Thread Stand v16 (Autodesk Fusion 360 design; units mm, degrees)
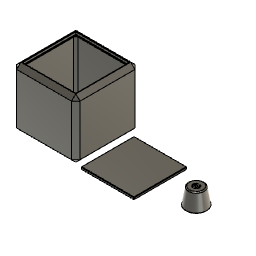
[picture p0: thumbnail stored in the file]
parameter "base_side_length" = 75
parameter "base_height" = 70
parameter "wire_hole_diameter" = 2.75 (= "wire_diameter + wire_hole_tolerance")
parameter "wire_hole_offset_from_corner" = 12
parameter "wire_hole_depth" = 30
parameter "spool_pin_diameter" = 6
parameter "spool_pin_height" = 20
parameter "big_chamfer_size" = 5
parameter "bottom_hole_offset" = 6
parameter "shell_thickness" = 4
parameter "bottom_hatch_side_length" = 63 (= "base_side_length - bottom_hole_offset * 2")
parameter "hatch_step_width" = 2
parameter "hatch_step_depth" = 3
parameter "hatch_side_tolerance" = 0.3
parameter "hatch_thickness_tolerance" = 0.2
parameter "wire_hole_tolerance" = 0.2
parameter "wire_diameter" = 2.55
parameter "spring_thickness" = 1.5
parameter "spring_gap" = 1
parameter "spring_bridge_width" = 2
parameter "cap_base" = 25
parameter "cap_base_taper" = 10
parameter "cap_height" = 20
sketch "Sketch2" plane through (0, 0, 0) normal (0, 0, 1) x axis (1, 0, 0)
  line L1 (-37.5, -37.5) -> (37.5, -37.5)
  line L2 (-37.5, 37.5) -> (-37.5, -37.5)
  line L3 (37.5, 37.5) -> (-37.5, 37.5)
  line L4 (37.5, -37.5) -> (37.5, 37.5)
  line L5 (-37.5, 37.5) -> (37.5, -37.5)
  line L6 (37.5, 37.5) -> (-37.5, -37.5)
  point P6 (0, 0)
  point P1 (0, 0)
  point P4 (-37.5, 37.5)
  point P5 (37.5, 37.5)
  point P3 (-37.5, -37.5)
  horizontal L1
  perpendicular L1 L2
  parallel L1 L3
  parallel L2 L4
  coincident L5 P6
  coincident L6 P6
  coincident P1 P6
  dimension "d7" distance P4 P5 = 75 (= "base_side_length")
  dimension "d8" distance P3 P4 = 75 (= "base_side_length")
extrude "Extrude2" new body sketch "Sketch2" profile of L1 L2 L3 L4 along normal blind 70 (= "base_height") bodies "Thread_Stand_Body"
sketch "Sketch3" plane through (0, 0, 70) normal (0, 0, 1) x axis (-1, 0, 0)
  line L1 (37.5, -37.5) -> (-37.5, -37.5)
  line L2 (37.5, 37.5) -> (37.5, -37.5)
  line L3 (-37.5, 37.5) -> (37.5, 37.5)
  line L4 (-37.5, -37.5) -> (-37.5, 37.5)
  line L5 (-37.5, 37.5) -> (37.5, -37.5)
  line L6 (37.5, 37.5) -> (-37.5, -37.5)
  circle C1 centre (29.0147, -29.0147) radius 1.375
  circle C2 centre (0, 0) radius 1.375
  point P3 (37.5, -37.5)
  point P7 (37.5, -37.5)
  point P5 (-37.5, 37.5)
  point P8 (-37.5, 37.5)
  point P6 (29.0147, -29.0147)
  point P2 (-37.5, -37.5)
  point P9 (-37.5, -37.5)
  point P4 (37.5, 37.5)
  point P10 (37.5, 37.5)
  point P1 (0, 0)
  point P11 (0, 0)
  coincident P3 P7
  coincident P5 P8
  coincident P6 L5
  coincident P2 P9
  coincident P4 P10
  coincident P1 P11
  dimension "d12" diameter C1 = 2.75 (= "wire_hole_diameter")
  dimension "d14" distance P6 P7 = 12 (= "wire_hole_offset_from_corner")
  dimension "d18" diameter C2 = 2.75 (= "wire_hole_diameter")
extrude "Extrude3" cut sketch "Sketch3" profile of C1 C2 no distance stored
chamfer "Chamfer1" distance 5 (= "big_chamfer_size")
chamfer "Chamfer2" distance 0.5
shell "Shell1" innerThickness 4 (= "shell_thickness")
sketch "Sketch4" plane through (0, 0, 0) normal (0, 0, -1) x axis (1, 0, 0)
  line L1 (-26.8431, -26.8431) -> (26.8431, -26.8431)
  line L2 (-26.8431, 26.8431) -> (-26.8431, -26.8431)
  line L3 (26.8431, 26.8431) -> (-26.8431, 26.8431)
  line L4 (26.8431, -26.8431) -> (26.8431, 26.8431)
  line L5 (32.5, -32.5) -> (-32.5, -32.5)
  line L6 (32.5, 32.5) -> (32.5, -32.5)
  line L7 (-32.5, 32.5) -> (32.5, 32.5)
  line L8 (-32.5, -32.5) -> (-32.5, 32.5)
  line L9 (31.5, -31.5) -> (-31.5, -31.5)
  line L10 (31.5, 31.5) -> (31.5, -31.5)
  line L11 (-31.5, 31.5) -> (31.5, 31.5)
  line L12 (-31.5, -31.5) -> (-31.5, 31.5)
  line L13 (31.5, 31.5) -> (-31.5, -31.5)
  line L14 (-31.5, 31.5) -> (31.5, -31.5)
  line L15 (-29.5, -29.5) -> (29.5, -29.5)
  line L16 (-29.5, 29.5) -> (-29.5, -29.5)
  line L17 (29.5, 29.5) -> (-29.5, 29.5)
  line L18 (29.5, -29.5) -> (29.5, 29.5)
  line L19 (-29.5, 29.5) -> (29.5, -29.5)
  line L20 (29.5, 29.5) -> (-29.5, -29.5)
  point P14 (0, 0)
  point P1 (0, 0)
  point P19 (0, 0)
  point P12 (31.5, 31.5)
  point P13 (-31.5, 31.5)
  point P15 (29.5, -29.5)
  point P18 (29.5, 29.5)
  horizontal L9
  perpendicular L9 L10
  parallel L9 L11
  parallel L10 L12
  coincident L13 P14
  coincident L14 P14
  coincident P1 P14
  horizontal L15
  perpendicular L15 L16
  parallel L15 L17
  parallel L16 L18
  coincident L19 P19
  coincident L20 P19
  coincident P14 P19
  equal L17 L18
  equal L11 L12
  dimension "d36" distance P12 P13 = 63 (= "bottom_hatch_side_length")
  dimension "d38" distance P15 P18 = 59 (= "bottom_hatch_side_length - hatch_step_width * 2")
chamfer "Chamfer3" distance 10 (= "wire_hole_depth / 3")
extrude "Extrude5" cut sketch "Sketch4" profile of L1 L2 L3 L4 L15 L16 L17 L18 against normal blind 8 (magnitude of "-shell_thickness * 2")
extrude "Extrude6" cut sketch "Sketch4" profile of L9 L10 L11 L12 L15 L16 L17 L18 no distance stored
sketch "Sketch6" plane through (0, 0, 0) normal (0, 0, 1) x axis (1, 0, 0)
  line L1 (137.7, 31.35) -> (75, 31.35)
  line L2 (137.7, -31.35) -> (137.7, 31.35)
  line L3 (75, -31.35) -> (137.7, -31.35)
  line L4 (75, 31.35) -> (75, -31.35)
  line L5 (137.7, -31.35) -> (75, 31.35)
  line L6 (75, -31.35) -> (137.7, 31.35)
  line L7 (137.7, 0) -> (0, 0)
  point P6 (106.35, 0)
  point P1 (0, 0)
  point P7 (0, 0)
  point P8 (137.7, 0)
  point P2 (75, 31.35)
  point P3 (137.7, 31.35)
  horizontal L1
  perpendicular L1 L2
  parallel L1 L3
  parallel L2 L4
  coincident L5 P6
  coincident L6 P6
  equal L1 L2
  coincident P1 P7
  coincident L2 P8
  perpendicular L2 L7
  coincident P6 L7
  dimension "d43" distance P2 P3 = 62.7 (= "bottom_hatch_side_length - hatch_side_tolerance")
  dimension "d44" distance P1 L4 = 75 (= "base_side_length")
extrude "Extrude7" new body sketch "Sketch6" profile of L1 L2 L3 L4 along normal blind 2.8 (= "hatch_step_depth - hatch_thickness_tolerance") bodies "Thread_Stand_Lid"
chamfer "Chamfer4" distance 0.5
chamfer "Chamfer5" distance 0.5
cylinder_primitive "CylinderPrimitive1" Height 15 Diameter 12 bodies "Test_Piece"
sketch "Sketch8" plane through (0, 0, 15) normal (0, 0, 1) x axis (-1, 0, 0)
  circle C1 centre (-55, 0) radius 6
  circle C2 centre (-55, 0) radius 1.375
  circle C3 centre (-55, 0) radius 1.425
  concentric C1 C2
  concentric C2 C3
  dimension "d53" diameter C2 = 2.75 (= "wire_hole_diameter")
  dimension "d58" diameter C3 = 2.85 (= "wire_hole_diameter + 0.1 mm")
extrude "Extrude8" cut sketch "Sketch8" profile of C2 no distance stored
extrude "Extrude9" cut sketch "Sketch8" profile of C2 C3 against normal blind 7.5
sketch "Sketch9" plane through (0, 0, 0) normal (0, 0, 1) x axis (1, 0, 0)
  line L1 (180, 0) -> (0, 0)
  line L2 (181, -2.5886) -> (179, -2.5886)
  line L3 (181, -3.6401) -> (181, -2.5886)
  line L4 (179, -3.6401) -> (181, -3.6401)
  line L5 (179, -2.5886) -> (179, -3.6401)
  line L6 (181, 3.6401) -> (179, 3.6401)
  line L7 (181, 2.5886) -> (181, 3.6401)
  line L8 (179, 2.5886) -> (181, 2.5886)
  line L9 (179, 3.6401) -> (179, 2.5886)
  line L10 (183.7417, -0.5) -> (176.2583, -0.5)
  line L11 (183.7417, 0.5) -> (183.7417, -0.5)
  line L12 (176.2583, 0.5) -> (183.7417, 0.5)
  line L13 (176.2583, -0.5) -> (176.2583, 0.5)
  circle C1 centre (180, 0) radius 12.5
  circle C2 centre (180, 0) radius 1.275
  circle C3 centre (180, 0) radius 2.775
  circle C4 centre (180, 0) radius 3.775
  point P1 (0, 0)
  point P3 (0, 0)
  point P2 (180, 0)
  point P4 (180, 0)
  point P11 (179, -3.6401)
  point P10 (181, -3.6401)
  point P9 (181, -2.5886)
  point P15 (179, 2.5886)
  point P14 (181, 2.5886)
  point P13 (181, 3.6401)
  point P16 (176.2583, -0.5)
  point P19 (176.2583, 0.5)
  point P18 (183.7417, 0.5)
  point P12 (179, 3.6401)
  point P17 (183.7417, -0.5)
  coincident P1 P3
  horizontal L1
  coincident P2 P4
  concentric C1 C2
  concentric C1 C3
  concentric C2 C4
  horizontal L2
  vertical L3
  horizontal L4
  vertical L5
  coincident C4 P11
  coincident C4 P10
  coincident C3 P9
  horizontal L6
  vertical L7
  horizontal L8
  vertical L9
  coincident C3 P15
  coincident C3 P14
  coincident C4 P13
  horizontal L10
  vertical L11
  horizontal L12
  vertical L13
  coincident C4 P16
  coincident C4 P19
  coincident C4 P18
  dimension "d61" diameter C1 = 25 (= "cap_base")
  dimension "d62" distance P3 P4 = 180
  dimension "d63" diameter C2 = 2.55 (= "wire_diameter")
  dimension "d65" diameter C3 = 5.55 (= "wire_diameter + 2 * spring_thickness")
  dimension "d67" diameter C4 = 7.55 (= "wire_diameter + 2 * spring_thickness + 2 * spring_gap")
  dimension "d69" distance P10 P11 = 2 (= "spring_bridge_width")
  dimension "d70" distance P12 P13 = 2 (= "spring_bridge_width")
  dimension "d71" distance P17 P18 = 1 (= "spring_gap")
extrude "Extrude10" new body sketch "Sketch9" profile of C1 C2 C3 C4 L2 L3 L4 L5 L6 L7 L8 L9 L10 L11 L12 L13 along normal blind 20 (= "cap_height") bodies "Thread_Cap"
extrude "Extrude11" cut sketch "Sketch9" profile of C2 C3 C4 L3 L5 L7 L9 L10 L11 L12 L13 no distance stored
chamfer "Chamfer7" distance 1
component_from_bodies "Body->Comp1"
component_from_bodies "Body->Comp2"
component_from_bodies "Body->Comp3"
ground "Ground1"
move "Move1" RotateAngle 180
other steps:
base_feature "Base Feature1" bodies "Thread_Stand_Body"
base_feature "Base Feature1" bodies "Thread_Cap"
base_feature "Base Feature1" bodies "Thread_Stand_Lid"
create_component "CreateComponent1"
remove_body "RemoveBody1"
create_component "CreateComponent2"
remove_body "RemoveBody2"
create_component "CreateComponent3"
remove_body "RemoveBody3"
named bodies: "Thread_Stand_Body", "Thread_Stand_Lid", "Test_Piece", "Thread_Cap"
